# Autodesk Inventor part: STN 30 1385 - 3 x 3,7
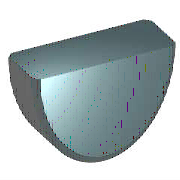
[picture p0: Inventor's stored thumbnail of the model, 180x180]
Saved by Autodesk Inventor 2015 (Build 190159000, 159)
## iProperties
Created: 2011-02
Part Number: STN 30 1385 - 3 x 3,7
Material: Měkká ocel
Description: Woodruffovo pero
Document SubType Name: Modeling
Standard: STN 30 1385
Designer: Marián Mičúch
Standards Organization: STN
Language: cs-CZ
Size Designation: 3 x 3,7
Categories: <MemberInstance><Categories><Category DisplayName="Součásti hřídele" InternalName="7f7aeb1f-a693-4053-b835-cee3144e0d98" Mnemonic="SHFT"><Category DisplayName="
Density: 1 g/cm^3
Appearance: Ocel
IsCustomPart: 0
Author: Marián Mičúch
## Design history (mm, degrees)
sketch "Náčrt1"
  geometry: L1 (-4.828, -1)-(4.828, -1); L2 (-4, 2.7)-(5, 2.7); L3 (0, 13)-(0, -9.4) reference; L4 (-22.003, 0)-(22.003, 0) reference; A1 r 5 centre (0, -2.3) between (4.828, -1) and (-4.828, -1)
  constraints: 4 end point, 2 point on circle, 1 centre point, 1 horizontal, 1 point on line, 1 tangent
  dimensions: "d1" = 3.7 distance between parallel lines of L2 L1 (= PH); "d2" = 2.7 distance between parallel lines of L4 L2 (= PWT); "d12" = 10 diameter of A1 (= PD2)
extrude "Těleso" new body sketch "Náčrt1" stored distance "d3" = 3 (= PB); taper "d4" = 0 deg
body "Solid1"
chamfer "Zkosení1" distance "d8" = 0.2001 (computed from PHH); stored, may be unused: second distance "d9" = 0.2001 (computed from PHH), angle "d11" = 45 deg
other parameters: "PB" = 3 [user parameter; used in 1 equation term], "PH" = 3.7 [user parameter; used in 1 equation term], "PD2" = 10 [user parameter; used in 1 equation term], "PWT" = 2.7 [user parameter; used in 1 equation term], "d5" = 0, "PHH" = 0.2 (= RR) [user parameter; used in 2 equation terms], "d13" = 0, "d14" = 0, "NLG" = 9.66 [user parameter], "WDMAX" = 12 [user parameter], "RR" = 0.2 [user parameter; used in 1 equation term], "PUEB" = 1.1 [user parameter]
